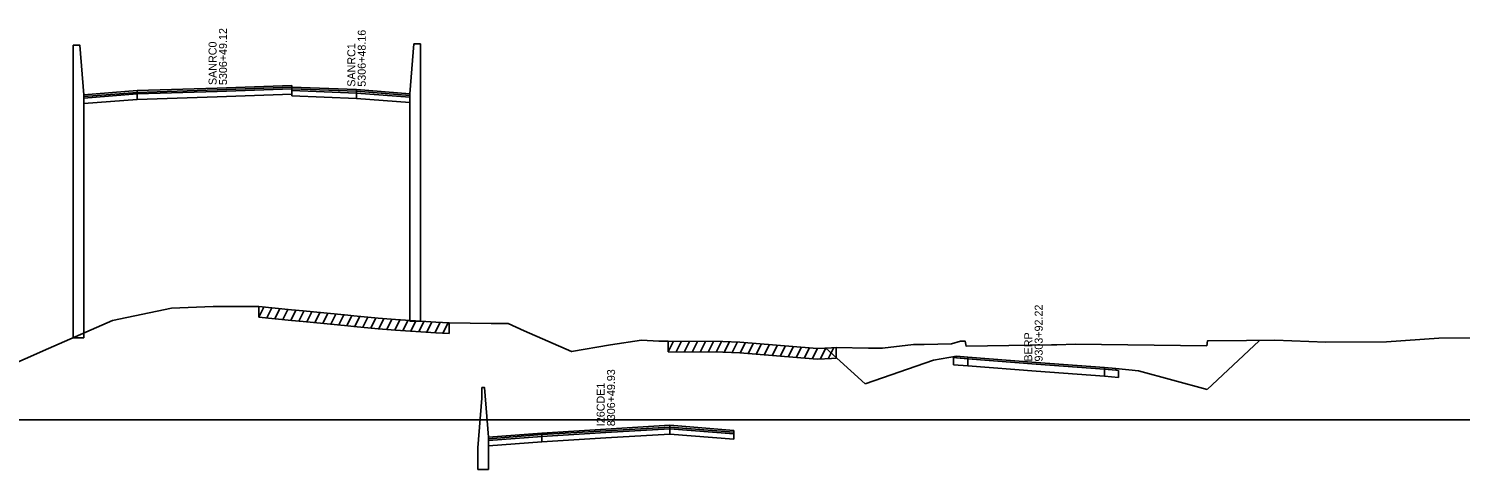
# Model space of a CAD drawing. Extents: x 1017 to 19997, y -1947 to 50737.
# Drawn here: x 12687.3 to 12955.6, y 6490.8 to 6573.2 of the extents above; entities that cross this region are included whole.
import ezdxf

# ---------------------------------------------------------------- set-up
doc = ezdxf.new("R2010")
doc.units = 0
for name, color, linetype in [('RD_GPK_XS_Cell', 7, 'Continuous'), ('RD_XS_Base', 7, 'Continuous'), ('RD_XS_ExGround', 7, 'Continuous'), ('RD_XS_ExPaveRet', 7, 'Continuous'), ('RD_XS_Greenside', 7, 'Continuous'), ('RD_XS_MedBWall', 7, 'Continuous'), ('RD_XS_Pave', 7, 'Continuous'), ('RD_XS_PaveOvlay', 7, 'Continuous'), ('RD_XS_TieSlope', 7, 'Continuous'), ('RD_XS_TX_Notes', 7, 'Continuous')]:
    doc.layers.add(name, color=color, linetype=linetype)

msp = doc.modelspace()

# ---------------------------------------------------------------- linework, layer by layer
at = {"layer": 'RD_GPK_XS_Cell'}
msp.add_line((12600, 6500), (13200, 6500), dxfattribs=at)
at = {"layer": 'RD_XS_Base'}
for points in [[(12707.63, 6561), (12697.63, 6560.2)], [(12697.63, 6560.2), (12697.63, 6559.2)], [(12697.63, 6559.2), (12707.63, 6560)], [(12707.63, 6561), (12722.62, 6561.48), (12736.62, 6561.94)], [(12707.63, 6560), (12707.63, 6561)], [(12736.62, 6560.94), (12722.62, 6560.48), (12707.63, 6560)], [(12736.62, 6561.94), (12736.62, 6560.94)], [(12736.64, 6561.66), (12748.74, 6561.18)], [(12736.64, 6560.66), (12736.64, 6561.66)], [(12748.74, 6560.18), (12736.64, 6560.66)], [(12748.74, 6561.18), (12758.74, 6560.4)], [(12748.74, 6560.18), (12748.74, 6561.18)], [(12758.74, 6559.4), (12748.74, 6560.18)], [(12758.74, 6560.4), (12758.74, 6559.4)], [(12860.61, 6511.67), (12860.61, 6510.33)], [(12863.28, 6511.46), (12860.61, 6511.67)], [(12863.28, 6511.46), (12876.08, 6510.46), (12888.89, 6509.48)], [(12863.28, 6510.12), (12863.28, 6511.46)], [(12860.61, 6510.33), (12863.28, 6510.12)], [(12888.89, 6508.17), (12876.08, 6509.12), (12863.28, 6510.12)], [(12888.89, 6509.48), (12888.89, 6508.17)], [(12888.89, 6509.48), (12891.02, 6509.32), (12891.55, 6509.28)], [(12891.55, 6509.28), (12891.55, 6507.95)], [(12891.55, 6507.95), (12888.89, 6508.17)], [(12783.46, 6496.92), (12795.46, 6497.63), (12807.46, 6498.35)], [(12807.46, 6498.35), (12807.46, 6497.35)], [(12819.46, 6497.38), (12807.46, 6498.35)], [(12783.46, 6496.92), (12773.46, 6496.12)], [(12773.46, 6496.12), (12773.46, 6495.12)], [(12773.46, 6495.12), (12783.46, 6495.92)], [(12807.46, 6497.35), (12795.46, 6496.63), (12783.46, 6495.92)], [(12783.46, 6495.92), (12783.46, 6496.92)], [(12807.46, 6497.35), (12819.46, 6496.38)], [(12819.46, 6496.38), (12819.46, 6497.38)]]:
    msp.add_lwpolyline(points, dxfattribs=at)
at = {"layer": 'RD_XS_ExGround'}
msp.add_lwpolyline([(12682.25, 6509.52), (12691.05, 6513.37), (12703.01, 6518.58), (12714.09, 6520.93), (12721.87, 6521.22), (12722.89, 6521.23), (12728.79, 6521.23), (12730.41, 6521.23), (12736.56, 6520.6), (12738.77, 6520.39), (12747.14, 6519.6), (12748.24, 6519.49), (12752.81, 6519.06), (12756.05, 6518.78), (12763.6, 6518.31), (12766.11, 6518.16), (12773.99, 6518.04), (12775.46, 6518.02), (12777.16, 6518.02), (12780.16, 6516.69), (12789.05, 6512.79), (12796.34, 6514.08), (12802.13, 6514.91), (12805.42, 6514.74), (12807.15, 6514.72), (12817.36, 6514.67), (12820.56, 6514.58), (12834.29, 6513.43), (12835.21, 6513.34), (12837.73, 6513.5), (12838.62, 6513.55), (12844.65, 6513.41), (12847.33, 6513.4), (12853.09, 6514.12), (12855.14, 6514.09), (12860.24, 6514.22), (12861.95, 6514.74), (12862.43, 6514.74), (12862.82, 6514.73), (12862.98, 6513.82), (12878.99, 6514.05), (12879.57, 6514.06), (12879.96, 6514.08), (12883.42, 6514.17), (12908.06, 6513.89), (12908.18, 6514.8), (12915.5, 6514.85), (12920.8, 6514.93), (12930.4, 6514.53), (12941.75, 6514.61), (12951.56, 6515.32), (12962.65, 6515.35)], dxfattribs=at)
at = {"layer": 'RD_XS_ExPaveRet'}
for p, q in [((12730.41, 6519.23), (12730.41, 6521.23)), ((12730.41, 6519.23), (12731.37, 6521.13)), ((12731.91, 6519.08), (12732.87, 6520.98)), ((12733.41, 6518.92), (12734.37, 6520.83)), ((12734.91, 6518.77), (12735.87, 6520.67)), ((12736.41, 6518.62), (12737.37, 6520.52)), ((12737.91, 6518.47), (12738.87, 6520.38)), ((12739.41, 6518.33), (12740.37, 6520.24)), ((12740.91, 6518.19), (12741.87, 6520.1)), ((12742.41, 6518.05), (12743.37, 6519.96)), ((12743.91, 6517.91), (12744.87, 6519.82)), ((12745.41, 6517.77), (12746.37, 6519.68)), ((12746.91, 6517.63), (12747.87, 6519.53)), ((12748.41, 6517.48), (12749.37, 6519.39)), ((12730.41, 6519.23), (12736.56, 6518.6)), ((12736.56, 6518.6), (12738.77, 6518.39)), ((12738.77, 6518.39), (12747.14, 6517.6)), ((12747.14, 6517.6), (12748.24, 6517.49)), ((12748.24, 6517.49), (12752.81, 6517.06)), ((12749.91, 6517.33), (12750.87, 6519.24)), ((12751.41, 6517.19), (12752.37, 6519.1)), ((12752.81, 6517.06), (12756.05, 6516.78)), ((12752.91, 6517.05), (12753.87, 6518.97)), ((12754.41, 6516.92), (12755.37, 6518.84)), ((12755.91, 6516.79), (12756.88, 6518.73)), ((12756.05, 6516.78), (12763.6, 6516.31)), ((12757.41, 6516.69), (12758.38, 6518.63)), ((12758.91, 6516.6), (12759.88, 6518.54)), ((12760.41, 6516.51), (12761.38, 6518.45)), ((12761.91, 6516.41), (12762.88, 6518.35)), ((12763.41, 6516.32), (12764.39, 6518.26)), ((12764.91, 6516.23), (12765.89, 6518.17)), ((12766.11, 6518.16), (12766.11, 6516.16)), ((12763.6, 6516.31), (12766.11, 6516.16)), ((12807.15, 6512.72), (12808.15, 6514.72)), ((12807.15, 6512.72), (12807.15, 6514.72)), ((12808.65, 6512.72), (12809.65, 6514.71)), ((12810.15, 6512.71), (12811.15, 6514.7)), ((12811.65, 6512.7), (12812.65, 6514.69)), ((12813.15, 6512.69), (12814.15, 6514.69)), ((12814.65, 6512.68), (12815.65, 6514.68)), ((12816.15, 6512.68), (12817.15, 6514.67)), ((12817.65, 6512.66), (12818.64, 6514.63)), ((12819.15, 6512.62), (12820.14, 6514.59)), ((12820.65, 6512.57), (12821.61, 6514.49)), ((12822.15, 6512.45), (12823.11, 6514.37)), ((12823.65, 6512.32), (12824.61, 6514.24)), ((12825.15, 6512.19), (12826.11, 6514.11)), ((12826.65, 6512.07), (12827.61, 6513.99)), ((12807.15, 6512.72), (12817.36, 6512.67)), ((12817.36, 6512.67), (12820.56, 6512.58)), ((12820.56, 6512.58), (12834.29, 6511.43)), ((12828.15, 6511.94), (12829.11, 6513.86)), ((12829.65, 6511.82), (12830.61, 6513.74)), ((12831.15, 6511.69), (12832.11, 6513.61)), ((12832.65, 6511.56), (12833.61, 6513.48)), ((12834.15, 6511.44), (12835.11, 6513.35)), ((12834.29, 6511.43), (12835.21, 6511.34)), ((12835.21, 6511.34), (12837.73, 6511.5)), ((12835.65, 6511.37), (12836.68, 6513.43)), ((12837.15, 6511.46), (12838.18, 6513.53)), ((12837.73, 6511.5), (12838.62, 6511.55)), ((12838.62, 6513.55), (12838.62, 6511.55))]:
    msp.add_line(p, q, dxfattribs=at)
at = {"layer": 'RD_XS_Greenside'}
for points in [[(12861.15, 6511.94), (12856.88, 6511.16)], [(12856.88, 6511.16), (12844.07, 6506.74)], [(12891.02, 6509.64), (12895.29, 6509.16)], [(12895.29, 6509.16), (12908.17, 6505.67)]]:
    msp.add_lwpolyline(points, dxfattribs=at)
at = {"layer": 'RD_XS_MedBWall'}
for points in [[(12760.74, 6570.38), (12759.49, 6570.37), (12758.74, 6561.03)], [(12760.74, 6518.5), (12760.74, 6570.38)], [(12695.63, 6515.38), (12695.63, 6570.17)], [(12695.63, 6570.17), (12696.88, 6570.17), (12697.63, 6560.83)], [(12697.63, 6560.83), (12697.63, 6515.38)], [(12758.74, 6561.03), (12758.74, 6518.5)], [(12758.74, 6518.5), (12760.74, 6518.5)], [(12697.63, 6515.38), (12695.63, 6515.38)], [(12773.46, 6496.75), (12772.71, 6506.09), (12772.21, 6506.09)], [(12772.21, 6506.09), (12772.21, 6504.09)], [(12772.21, 6504.09), (12771.46, 6494.75)], [(12773.46, 6490.75), (12773.46, 6496.75)], [(12771.46, 6494.75), (12771.46, 6490.75)], [(12771.46, 6490.75), (12773.46, 6490.75)]]:
    msp.add_lwpolyline(points, dxfattribs=at)
at = {"layer": 'RD_XS_Pave'}
for points in [[(12736.62, 6562.26), (12722.62, 6561.8), (12707.63, 6561.31)], [(12736.62, 6561.94), (12736.62, 6562.26)], [(12707.63, 6561.31), (12697.63, 6560.51)], [(12697.63, 6560.2), (12707.63, 6561)], [(12697.63, 6560.51), (12697.63, 6560.2)], [(12707.63, 6561), (12722.62, 6561.48), (12736.62, 6561.94)], [(12707.63, 6561.31), (12707.63, 6561)], [(12748.74, 6561.5), (12736.64, 6561.97)], [(12736.64, 6561.97), (12736.64, 6561.66)], [(12736.64, 6561.66), (12748.74, 6561.18)], [(12748.74, 6561.18), (12748.74, 6561.5)], [(12748.74, 6561.5), (12758.74, 6560.72)], [(12758.74, 6560.4), (12748.74, 6561.18)], [(12758.74, 6560.72), (12758.74, 6560.4)], [(12807.46, 6498.67), (12795.46, 6497.95), (12783.46, 6497.24)], [(12783.46, 6496.92), (12795.46, 6497.63), (12807.46, 6498.35)], [(12807.46, 6498.35), (12807.46, 6498.67)], [(12807.46, 6498.67), (12819.46, 6497.71)], [(12819.46, 6497.38), (12807.46, 6498.35)], [(12773.46, 6496.43), (12783.46, 6497.24)], [(12783.46, 6496.92), (12773.46, 6496.12)], [(12773.46, 6496.12), (12773.46, 6496.43)], [(12783.46, 6497.24), (12783.46, 6496.92)], [(12819.46, 6497.71), (12819.46, 6497.38)]]:
    msp.add_lwpolyline(points, dxfattribs=at)
at = {"layer": 'RD_XS_PaveOvlay'}
for points in [[(12707.63, 6561.63), (12722.62, 6562.12), (12736.62, 6562.57)], [(12736.62, 6562.26), (12722.62, 6561.8), (12707.63, 6561.31)], [(12736.62, 6562.57), (12736.62, 6562.26)], [(12736.64, 6562.29), (12748.74, 6561.82)], [(12736.64, 6561.97), (12736.64, 6562.29)], [(12707.63, 6561.63), (12697.63, 6560.83)], [(12697.63, 6560.51), (12707.63, 6561.31)], [(12697.63, 6560.83), (12697.63, 6560.51)], [(12707.63, 6561.31), (12707.63, 6561.63)], [(12748.74, 6561.5), (12736.64, 6561.97)], [(12748.74, 6561.82), (12748.74, 6561.5)], [(12748.74, 6561.82), (12758.74, 6561.03)], [(12758.74, 6560.72), (12748.74, 6561.5)], [(12758.74, 6561.03), (12758.74, 6560.72)], [(12861.15, 6511.94), (12861.15, 6511.62)], [(12863.28, 6511.77), (12861.15, 6511.94)], [(12861.15, 6511.62), (12863.28, 6511.46)], [(12863.28, 6511.77), (12876.08, 6510.77), (12888.89, 6509.8)], [(12863.28, 6511.46), (12863.28, 6511.77)], [(12888.89, 6509.8), (12888.89, 6509.48)], [(12888.89, 6509.8), (12891.02, 6509.64)], [(12891.02, 6509.32), (12888.89, 6509.48)], [(12891.02, 6509.64), (12891.02, 6509.32)], [(12783.46, 6497.55), (12795.46, 6498.27), (12807.46, 6498.99)], [(12807.46, 6498.67), (12795.46, 6497.95), (12783.46, 6497.24)], [(12807.46, 6498.99), (12807.46, 6498.67)], [(12807.46, 6498.99), (12819.46, 6498.03)], [(12819.46, 6497.71), (12807.46, 6498.67)], [(12819.46, 6498.03), (12819.46, 6497.71)], [(12783.46, 6497.55), (12773.46, 6496.75)], [(12773.46, 6496.43), (12783.46, 6497.24)], [(12773.46, 6496.75), (12773.46, 6496.43)], [(12783.46, 6497.24), (12783.46, 6497.55)]]:
    msp.add_lwpolyline(points, dxfattribs=at)
at = {"layer": 'RD_XS_TieSlope'}
for points in [[(12908.17, 6505.67), (12917.9, 6514.83)], [(12844.07, 6506.74), (12836.71, 6513.42)]]:
    msp.add_lwpolyline(points, dxfattribs=at)

# ---------------------------------------------------------------- texts
at = {"layer": 'RD_XS_TX_Notes'}
for s, p in [(' 5306+49.12', (12724.47, 6562.12)), (' SANRC0', (12722.52, 6562.12)), (' SANRC1', (12748.52, 6561.81)), (' 5306+48.16', (12750.47, 6561.81)), (' 9303+92.22', (12877.32, 6510.37)), (' BERP', (12875.36, 6510.37)), (' 8306+49.93', (12797.19, 6498.27)), (' I26CDE1', (12795.24, 6498.27))]:
    msp.add_text(s, height=1.5, rotation=90, dxfattribs=at).set_placement(p)

doc.saveas('drawing.dxf')
